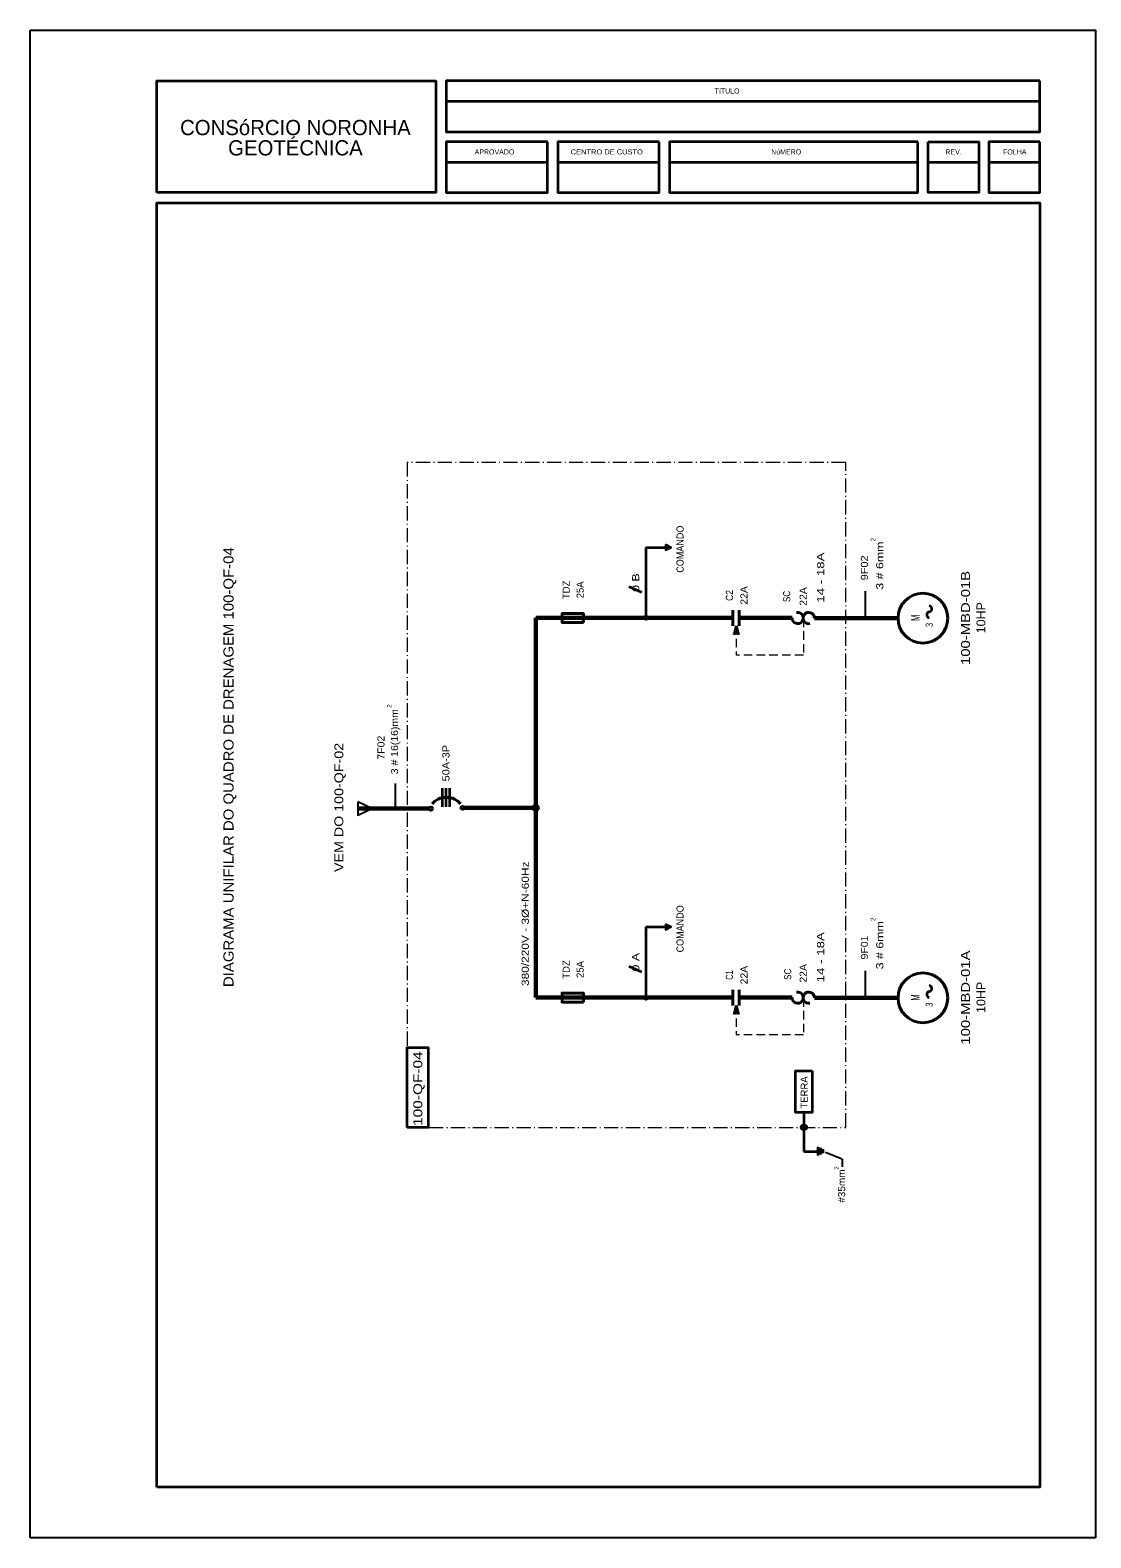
# Model space of a CAD drawing. Extents: x -4160 to -2690, y -474 to 714.
# Drawn here: x -4159.8 to -3950.7, y -176.5 to 120.5 of the extents above; entities that cross this region are included whole.
import ezdxf
from ezdxf.enums import TextEntityAlignment as Align

# ---------------------------------------------------------------- set-up
doc = ezdxf.new("R2010")
doc.units = 0
doc.header["$LTSCALE"] = 0.56
doc.linetypes.add('DOT_DASHED', pattern=[7.7, 5, -1.2, 0.3, -1.2])
doc.linetypes.add('MEDIUM_DASHED', pattern=[4.5, 3, -1.5])
for name, color, linetype, lineweight in [('1', 7, 'Continuous', 25), ('4', 7, 'Continuous', 25), ('5', 7, 'Continuous', 35)]:
    doc.layers.add(name, color=color, linetype=linetype, lineweight=lineweight)

msp = doc.modelspace()

# ---------------------------------------------------------------- hatches: boundary and pattern name
at = {"layer": '1'}
for points in [[(-4038.37, 5.1139, 1), (-4038.37, 4.3919, 1)], [(-4060.1138, -32.1843, 1), (-4060.1138, -33.2343, 1)], [(-4038.37, -69.7419, 1), (-4038.37, -70.464, 1)]]:
    msp.add_hatch(color=256, dxfattribs=at).paths.add_polyline_path(points)
at = {"layer": '5'}
msp.add_hatch(color=256, dxfattribs=at).paths.add_polyline_path([(-4007.2443, -95.1332, 1), (-4007.2443, -96.1832, 1)])

# ---------------------------------------------------------------- linework, layer by layer
at = {"layer": '1', "lineweight": 35}
for p, q in [((-4039.1582, 9.7024), (-4041.6592, 10.8112)), ((-4020.622, 3.1104), (-4021.0797, 1.3827)), ((-4020.622, 3.1104), (-4020.1642, 1.3827)), ((-4078.5011, -32.5332), (-4078.5011, -28.8673)), ((-4077.7673, -32.5332), (-4077.7673, -28.8673)), ((-4077.0335, -32.5332), (-4077.0335, -28.8673)), ((-4039.1582, -65.0848), (-4041.6592, -63.976)), ((-4020.622, -71.6768), (-4021.0797, -73.4045)), ((-4020.622, -71.6768), (-4020.1642, -73.4045))]:
    msp.add_line(p, q, dxfattribs=at)
at = {"layer": '1'}
for p, q in [((-3995.1754, 9.9517), (-3995.1754, 4.8902)), ((-3995.1754, -64.8354), (-3995.1754, -69.8969))]:
    msp.add_line(p, q, dxfattribs=at)
at = {"layer": '1', "lineweight": 40}
for p, q in [((-4021.2748, 3.1536), (-4021.2748, 6.2148)), ((-4020.0036, 3.1536), (-4020.0036, 6.2148)), ((-4021.2748, -71.6336), (-4021.2748, -68.5723)), ((-4020.0036, -71.6336), (-4020.0036, -68.5723))]:
    msp.add_line(p, q, dxfattribs=at)
at = {"layer": '1', "lineweight": 60}
for p, q in [((-4060.1138, 4.6842), (-4060.1138, -70.1029)), ((-4060.1138, 4.6842), (-4021.2748, 4.6842)), ((-4020.0036, 4.6842), (-4009.5887, 4.6842)), ((-4005.1789, 4.6592), (-3988.6884, 4.6592)), ((-4095.1751, -32.858), (-4081.1445, -32.858)), ((-4074.1445, -32.7094), (-4060.1138, -32.7094)), ((-4060.1138, -70.1029), (-4021.2748, -70.1029)), ((-4020.0036, -70.1029), (-4009.5887, -70.1029)), ((-4005.1789, -70.128), (-3988.6884, -70.128))]:
    msp.add_line(p, q, dxfattribs=at)
at = {"layer": '1', "linetype": 'MEDIUM_DASHED', "lineweight": 13}
for p, q in [((-4020.622, 3.1104), (-4020.622, -2.6317)), ((-4007.3485, 4.584), (-4007.3485, -2.6317)), ((-4007.3485, -2.6317), (-4020.622, -2.6317)), ((-4020.622, -71.6768), (-4020.622, -77.4188))]:
    msp.add_line(p, q, dxfattribs=at)
at = {"layer": '1'}
for points in [[(-4034.5485, 19.1277), (-4034.5485, 18.0696), (-4033.4348, 18.5987)], [(-4034.5485, -55.6594), (-4034.5485, -56.7176), (-4033.4348, -56.1885)]]:
    msp.add_lwpolyline(points, close=True, dxfattribs=at)
at = {"layer": '1', "lineweight": 40}
for points in [[(-4050.7185, 3.8024), (-4054.9015, 3.8024), (-4054.9015, 5.566), (-4050.7185, 5.566)], [(-4050.7185, -70.9847), (-4054.9015, -70.9847), (-4054.9015, -69.2212), (-4050.7185, -69.2212)]]:
    msp.add_lwpolyline(points, close=True, dxfattribs=at)
at = {"layer": '1', "linetype": 'MEDIUM_DASHED', "lineweight": 13}
msp.add_lwpolyline([(-4007.3485, -70.2031), (-4007.3485, -77.4188), (-4020.622, -77.4188)], dxfattribs=at)
at = {"layer": '1', "lineweight": 40}
for centre in [(-3983.7814, 4.6591), (-3983.7814, -70.1281)]:
    msp.add_circle(centre, 4.907, dxfattribs=at)
at = {"layer": '1', "lineweight": 35}
for centre, radius in [((-4038.37, 4.7529), 0.361), ((-4080.7945, -32.8581), 0.35), ((-4074.4945, -32.7094), 0.35), ((-4060.1138, -32.7093), 0.525), ((-4038.37, -70.1029), 0.361)]:
    msp.add_circle(centre, radius, dxfattribs=at)
for centre, start, end in [((-3982.6204, 6.5024), 279.02464, 82.50113), ((-3982.4489, 5.3212), 97.49887, 260.97536), ((-3982.6204, -68.2848), 279.02464, 82.50113), ((-3982.4489, -69.466), 97.49887, 260.97536)]:
    msp.add_arc(centre, 0.5969, start, end, dxfattribs=at)
at = {"layer": '1', "lineweight": 40}
for centre, start, end in [((-4008.4769, 4.6841), 179.99893, 100.86614), ((-4006.2907, 4.6659), 359.99893, 280.86614), ((-4008.4769, -70.103), 179.99893, 100.86614), ((-4006.2907, -70.1213), 359.99893, 280.86614)]:
    msp.add_arc(centre, 1.1118, start, end, dxfattribs=at)
msp.add_ellipse((-4077.7188, -33.4836), major_axis=(-3.3351, 0), ratio=0.85, start_param=3.72133334, end_param=5.70344457, dxfattribs=at)
at = {"layer": '4', "lineweight": 35}
for p, q in [((-4038.37, 18.5987), (-4038.37, 4.7529)), ((-4038.37, 18.5987), (-4033.4348, 18.5987)), ((-4038.37, -56.1885), (-4038.37, -70.1029)), ((-4038.37, -56.1885), (-4033.4348, -56.1885))]:
    msp.add_line(p, q, dxfattribs=at)
at = {"layer": '4'}
msp.add_line((-4087.8097, -27.9322), (-4087.8097, -32.858), dxfattribs=at)
at = {"layer": '4', "linetype": 'DOT_DASHED', "lineweight": 13}
msp.add_lwpolyline([(-3999.0027, -95.6581), (-3999.0027, 35.3308), (-4085.4552, 35.3308), (-4085.4552, -95.658)], close=True, dxfattribs=at)
at = {"layer": '4'}
msp.add_lwpolyline([(-4095.1751, -31.5367), (-4095.1751, -34.1793), (-4092.3937, -32.858)], close=True, dxfattribs=at)
at = {"layer": '5', "lineweight": 25}
for p, q in [((-4159.7642, -176.52), (-4159.7642, 120.48)), ((-3999.6935, -101.9172), (-4002.9577, -100.617)), ((-3999.6935, -101.9172), (-3999.6935, -103.4084)), ((-3949.7642, -176.52), (-4159.7642, -176.52))]:
    msp.add_line(p, q, dxfattribs=at)
at = {"layer": '5'}
for p, q in [((-4077.7642, 106.48), (-3960.7642, 106.48)), ((-4077.7642, 94.48), (-4057.7642, 94.48)), ((-4055.7642, 94.48), (-4035.7642, 94.48)), ((-4033.7642, 94.48), (-3984.7642, 94.48)), ((-3982.7642, 94.48), (-3972.7642, 94.48)), ((-3970.7642, 94.48), (-3960.7642, 94.48)), ((-4007.2443, -92.7497), (-4007.2443, -100.3868)), ((-4007.2443, -100.3868), (-4004.5233, -100.3868)), ((-4004.5233, -99.494), (-4004.5233, -101.1958)), ((-4004.001, -99.7135), (-4004.001, -100.9762)), ((-4003.4837, -99.9334), (-4003.4837, -100.7295))]:
    msp.add_line(p, q, dxfattribs=at)
at = {"layer": '5', "lineweight": 25}
msp.add_lwpolyline([(-4159.7642, 120.48), (-3949.7642, 120.48), (-3949.7642, -176.52)], dxfattribs=at)
at = {"layer": '5'}
for points in [[(-4134.7642, 88.48), (-4134.7642, 110.48), (-4079.7642, 110.48), (-4079.7642, 88.48)], [(-3960.7642, 110.48), (-4077.7642, 110.48), (-4077.7642, 100.48), (-3960.7642, 100.48)], [(-4057.7642, 98.48), (-4077.7642, 98.48), (-4077.7642, 88.48), (-4057.7642, 88.48)], [(-4035.7642, 98.48), (-4055.7642, 98.48), (-4055.7642, 88.48), (-4035.7642, 88.48)], [(-3984.7642, 98.48), (-4033.7642, 98.48), (-4033.7642, 88.48), (-3984.7642, 88.48)], [(-3982.7642, 98.48), (-3972.7642, 98.48), (-3972.7642, 88.48), (-3982.7642, 88.48)], [(-3960.7642, 98.48), (-3970.7642, 98.48), (-3970.7642, 88.48), (-3960.7642, 88.48)], [(-4134.7642, -166.52), (-4134.7642, 86.48), (-3960.7642, 86.48), (-3960.7642, -166.52)], [(-4085.4552, -95.658), (-4085.4552, -79.9048), (-4081.3361, -79.9048), (-4081.3361, -95.658)], [(-4005.6166, -84.547), (-4005.6166, -92.7497), (-4008.8721, -92.7497), (-4008.8721, -84.547)]]:
    msp.add_lwpolyline(points, close=True, dxfattribs=at)
msp.add_circle((-4007.2443, -95.6582), 0.525, dxfattribs=at)

# ---------------------------------------------------------------- texts
at = {"layer": '1', "width": 1.1}
msp.add_text('DIAGRAMA UNIFILAR DO QUADRO DE DRENAGEM 100-QF-04', height=2, rotation=90, dxfattribs=at).set_placement((-4119.6617, -68.0231))
at = {"layer": '1'}
for s, height, width, p in [('0 B', 1.4, 1.3, (-4039.7033, 11.6625)), ('100-MBD-01B', 1.75, 1.25, (-3974.5192, 4.6902)), ('10HP', 1.75, 1.05, (-3971.4762, 4.7317)), ('M', 1.75, 0.65, (-3984.3963, 4.7157)), ('3', 1.4, 0.8, (-3981.849, 3.3026)), ('50A-3P', 1.4, 1.15, (-4077.1071, -23.9094)), ('0 A', 1.4, 1.3, (-4039.7033, -63.1247)), ('100-MBD-01A', 1.75, 1.25, (-3974.5192, -70.0969)), ('10HP', 1.75, 1.05, (-3971.4762, -70.0555)), ('M', 1.75, 0.65, (-3984.3963, -70.0714)), ('3', 1.4, 0.8, (-3981.849, -71.4847))]:
    msp.add_text(s, height=height, rotation=90, dxfattribs=dict(at, width=width)).set_placement(p, align=Align.CENTER)
at = {"layer": '4'}
for s, height, width, p in [('COMANDO', 1.4, 0.95, (-4030.9593, 18.236)), ('2', 0.9185, 0.8, (-3993.1615, 20.1035)), ('3 # 6mm', 1.4, 1.3, (-3991.5935, 14.9957)), ('14 - 18A', 1.4, 1.4, (-4003.2479, 12.6311)), ('9F02', 1.4, 1.15, (-3994.6184, 14.559)), ('C2', 1.4, 0.9, (-4021.2351, 9.1171)), ('22A', 1.4, 1.1, (-4018.3474, 9.1208)), ('SC', 1.4, 0.85, (-4009.9342, 8.9174)), ('22A', 1.4, 1.1, (-4006.6814, 8.9139)), ('2', 0.9185, 0.8, (-4088.4852, -12.6702)), ('3 # 16(16)mm', 1.4, 1.1, (-4087.2419, -19.6886)), ('VEM DO 100-QF-02', 1.75, 1.2, (-4098.0353, -32.6374)), ('7F02', 1.4, 1.1, (-4089.9078, -20.8592)), ('380/220V - 3Ø+N-60Hz', 1.4, 1.25, (-4061.4676, -55.5564)), ('COMANDO', 1.4, 0.95, (-4030.9593, -56.5512)), ('2', 0.9185, 0.8, (-3993.1615, -54.6837)), ('3 # 6mm', 1.4, 1.3, (-3991.5935, -59.7915)), ('14 - 18A', 1.4, 1.4, (-4003.2479, -62.1561)), ('9F01', 1.4, 1.1, (-3994.6184, -60.2283)), ('C1', 1.4, 0.75, (-4021.2351, -65.6701)), ('22A', 1.4, 1.1, (-4018.3474, -65.6664)), ('SC', 1.4, 0.85, (-4009.7467, -65.4955)), ('22A', 1.4, 1.1, (-4006.6814, -65.3117))]:
    msp.add_text(s, height=height, rotation=90, dxfattribs=dict(at, width=width)).set_placement(p, align=Align.CENTER)
for s, p in [('TDZ', (-4053.4079, 10.2234)), ('25A', (-4050.6621, 10.2256)), ('TDZ', (-4053.4079, -64.5637)), ('25A', (-4050.6621, -64.5617))]:
    msp.add_text(s, height=1.4, rotation=90, dxfattribs=at).set_placement(p, align=Align.CENTER)
at = {"layer": '5'}
for s, height, p in [('TíTULO', 1, (-4022.3847, 107.991)), ('CONSóRCIO NORONHA', 3, (-4107.4749, 99.7961)), ('GEOTÉCNICA', 3, (-4107.4749, 95.7961)), ('APROVADO', 1, (-4068.2387, 95.9973)), ('REV.', 1, (-3977.7444, 95.9923)), ('FOLHA', 1, (-3965.681, 95.9923))]:
    msp.add_text(s, height=height, dxfattribs=at).set_placement(p, align=Align.CENTER)
for s, width, p in [('CENTRO DE CUSTO', 1.1, (-4046.0934, 95.9973)), ('NúMERO', 0.95, (-4010.7228, 95.9923))]:
    msp.add_text(s, height=1, dxfattribs=dict(at, width=width)).set_placement(p, align=Align.CENTER)
for s, height, width, p in [('100-QF-04', 1.75, 1.3, (-4082.4871, -88.0325)), ('2', 0.8267, 0.8, (-4000.3826, -103.6611)), ('#35mm', 1.4, 1.05, (-3999.1146, -107.2363))]:
    msp.add_text(s, height=height, rotation=90, dxfattribs=dict(at, width=width)).set_placement(p, align=Align.CENTER)
msp.add_text('TERRA', height=1.4, rotation=90, dxfattribs=at).set_placement((-4006.4736, -88.7897), align=Align.CENTER)

doc.saveas('drawing.dxf')
